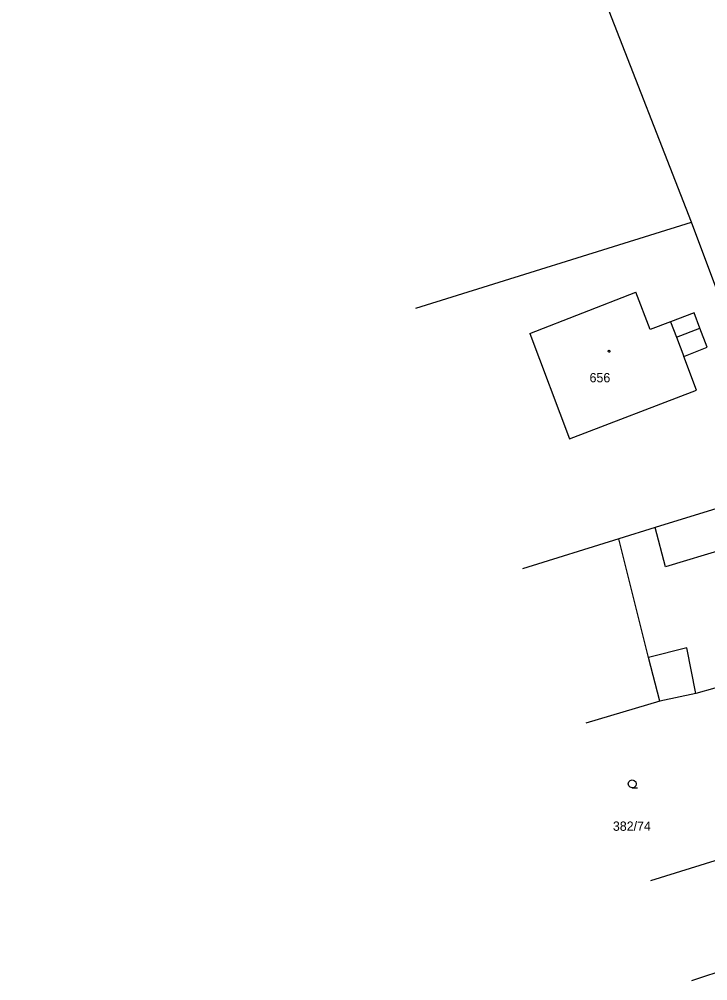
# Model space of a CAD drawing. Extents: x -757994 to -755874, y -1047691 to -1046119.
# Drawn here: x -757927.9 to -757864.8, y -1047255.1 to -1047167 of the extents above; entities that cross this region are included whole.
import ezdxf

# ---------------------------------------------------------------- set-up
doc = ezdxf.new("R2010")
doc.units = 0
doc.layers.add('katastrální mapa', color=7, linetype='Continuous')

msp = doc.modelspace()

# ---------------------------------------------------------------- linework, layer by layer
at = {"layer": 'katastrální mapa'}
for p, q in [((-757866.3, -1047185.62), (-757927.86, -1047028.05)), ((-757891.562, -1047193.503), (-757866.3, -1047185.62)), ((-757857.3, -1047209.77), (-757866.3, -1047185.62)), ((-757881.12, -1047195.81), (-757871.39, -1047192.02)), ((-757870.09, -1047195.45), (-757871.39, -1047192.02)), ((-757866.07, -1047193.92), (-757868.23, -1047194.74)), ((-757865.54, -1047195.32), (-757866.07, -1047193.92)), ((-757868.23, -1047194.74), (-757870.09, -1047195.45)), ((-757868.23, -1047194.74), (-757867.69, -1047196.15)), ((-757867.69, -1047196.15), (-757865.54, -1047195.32)), ((-757864.87, -1047197.07), (-757865.54, -1047195.32)), ((-757881.12, -1047195.81), (-757877.47, -1047205.44)), ((-757867.69, -1047196.15), (-757867.02, -1047197.9)), ((-757867.02, -1047197.9), (-757864.87, -1047197.07)), ((-757865.84, -1047200.99), (-757867.02, -1047197.9)), ((-757877.47, -1047205.44), (-757865.84, -1047200.99)), ((-757857.3, -1047209.77), (-757869.63, -1047213.56)), ((-757869.63, -1047213.56), (-757872.96, -1047214.6)), ((-757868.7, -1047217.17), (-757869.63, -1047213.56)), ((-757872.96, -1047214.6), (-757881.776, -1047217.351)), ((-757870.23, -1047225.47), (-757872.96, -1047214.6)), ((-757863.21, -1047215.52), (-757868.7, -1047217.17)), ((-757866.74, -1047224.6), (-757870.23, -1047225.47)), ((-757865.9, -1047228.78), (-757866.74, -1047224.6)), ((-757869.22, -1047229.49), (-757870.23, -1047225.47)), ((-757865.9, -1047228.78), (-757869.22, -1047229.49)), ((-757864.18, -1047228.29), (-757865.9, -1047228.78)), ((-757869.22, -1047229.49), (-757875.97, -1047231.501)), ((-757861.56, -1047243.29), (-757870.048, -1047245.933)), ((-757854.36, -1047251.15), (-757866.293, -1047255.085))]:
    msp.add_line(p, q, dxfattribs=at)
msp.add_lwpolyline([(-757873.86, -1047197.345), (-757873.81, -1047197.355), (-757873.785, -1047197.4), (-757873.775, -1047197.43), (-757873.785, -1047197.475), (-757873.825, -1047197.51), (-757873.86, -1047197.515), (-757873.905, -1047197.5), (-757873.935, -1047197.47), (-757873.945, -1047197.43), (-757873.935, -1047197.385), (-757873.895, -1047197.35)], close=True, dxfattribs=at)
msp.add_lwpolyline([(-757871.73, -1047237.42), (-757871.92, -1047237.37), (-757872.055, -1047237.235), (-757872.105, -1047237.05), (-757872.055, -1047236.865), (-757871.92, -1047236.73), (-757871.735, -1047236.68), (-757871.55, -1047236.73), (-757871.415, -1047236.865), (-757871.365, -1047237.055), (-757871.415, -1047237.245), (-757871.55, -1047237.38), (-757871.74, -1047237.43), (-757871.24, -1047237.43)], dxfattribs=at)

# ---------------------------------------------------------------- texts
for s, p in [('656', (-757875.641, -1047200.28)), ('382/74', (-757873.505, -1047241.35))]:
    msp.add_text(s, height=0.85, dxfattribs=at).set_placement(p)

doc.saveas('drawing.dxf')
